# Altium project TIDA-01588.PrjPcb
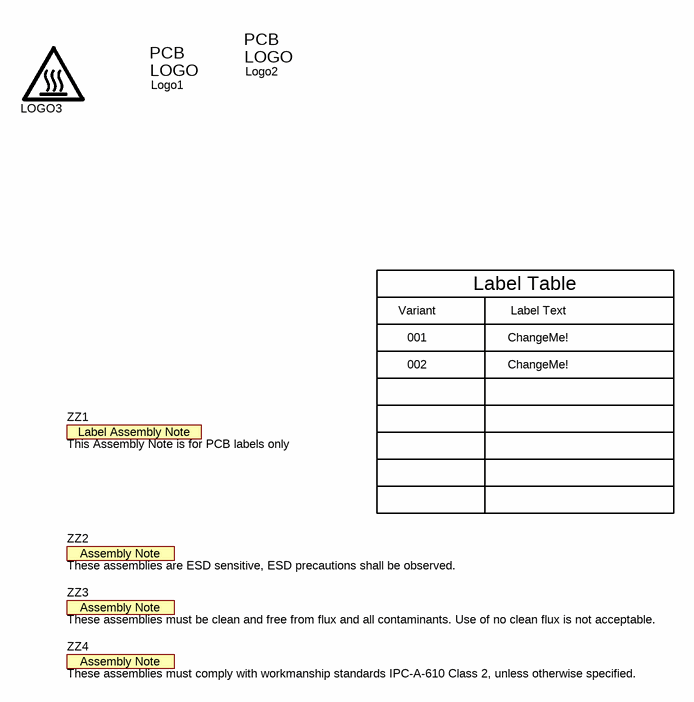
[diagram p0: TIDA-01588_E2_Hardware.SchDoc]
CopyrightYear: 2017; EVM_orderable: N/A; PCB_Layout: Manu; PCB_Rev: E2; PRJ_Customer: Public Release; PRJ_Engineer: Manu Balakrishnan; PRJ_Number: TIDA-01588; PRJ_Title: 10.8-V/15-W, Power Stage for Brushed DC Servo; SCH_Rev: E2; TechSupport: http://www.ti.com/support; TID: TIDA-01588
3 sheets, 50 parts. Net scope: global (net labels, ports and power ports of the same name join across sheets).
Board file: TIDA-01588_PCB.PcbDoc
Sheets:
  TIDA-01588_E2_CoverSheet.SchDoc
  TIDA-01588_E2_Hardware.SchDoc
  TIDA-01588_E2_Sheet1.SchDoc

## Sheet TIDA-01588_E2_CoverSheet.SchDoc
size 431 x 279 mm; Date: Not shown in title block; ApprovedBy: Not shown in title block; CheckedBy: Not shown in title block; Author: Not shown in title block; CompanyName: Not shown in title block; DrawnBy: Manu; Engineer: Not shown in title block; Organization: Not shown in title block; Address1: Not shown in title block; Address2: Not shown in title block; Address3: Not shown in title block; Address4: Not shown in title block; DocumentNumber: 1; Revision: Use project parameter SCH_Rev; SheetNumber: 1; SheetTotal: 3; PageSetup: Record=PageOptions¦CenterHorizontal=True¦CenterVertical=True¦PrintScale=1.00¦XCorrection=1.00¦YCorrection=1.00¦PrintKind=0¦BorderSize=5000000¦LeftOffset=0¦BottomOffset=0¦Orientation=2¦PaperLength=1000¦PaperWidth=1000¦Scale=100¦PaperSource=15¦PrintQuality=600¦MediaType=1¦DitherType=10¦PaperKind=Letter¦PrintScaleMode=1

## Sheet TIDA-01588_E2_Hardware.SchDoc
size 431 x 279 mm; Date: Not shown in title block; ApprovedBy: Not shown in title block; CheckedBy: Not shown in title block; Author: Not shown in title block; CompanyName: Not shown in title block; DrawnBy: Manu; Engineer: Not shown in title block; Organization: Not shown in title block; Address1: Not shown in title block; Address2: Not shown in title block; Address3: Not shown in title block; Address4: Not shown in title block; DocumentNumber: 1; Revision: Use project parameter SCH_Rev; SheetNumber: 3; SheetTotal: 3; PageSetup: Record=PageOptions¦CenterHorizontal=True¦CenterVertical=True¦PrintScale=1.00¦XCorrection=1.00¦YCorrection=1.00¦PrintKind=0¦BorderSize=5000000¦LeftOffset=0¦BottomOffset=0¦Orientation=2¦PaperLength=1000¦PaperWidth=1000¦Scale=100¦PaperSource=15¦PrintQuality=600¦MediaType=1¦DitherType=10¦PaperKind=Letter¦PrintScaleMode=1

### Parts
Logo1  ESD Susceptible  [ESD_Overlay_small]  (value not drawn)  (no BOM)
Logo2  Pb-Free Symbol  [Pb-Free_Overlay_small]  (value not drawn)  (no BOM)
LOGO3  CAUTION HOT SURFACE  [IEC_HotSurface_small]  (value not drawn)  (no BOM)
ZZ1  This Assembly Note is for PCB labels only  [AssemblyNoteLabel]  (no BOM)
ZZ2  These assemblies are ESD sensitive, ESD precautions shall be observed.  [AssemblyNote]  (no BOM)
ZZ3  These assemblies must be clean and free from flux and all contaminants. Use of no clean flux is not acceptable.  [AssemblyNote]  (no BOM)
ZZ4  These assemblies must comply with workmanship standards IPC-A-610 Class 2, unless otherwise specified.  [AssemblyNote]  (no BOM)

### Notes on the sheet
- Variant
- 001
- Label Table
- Label Text
- ChangeMe!
- 002

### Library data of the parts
Logo1 = ESD_Susceptible: ESD Susceptible Symbol; SymbolCreator: a0412235
Logo2 = Pb-Free: SymbolCreator: a0412235
LOGO3 = IEC_HotSurface: IEC 61010-1 Hot Surface Warning; SymbolCreator: a0412235
ZZ1 = AssemblyNoteLabel: SymbolCreator: a0412235
ZZ2-ZZ4 = AssemblyNote: SymbolCreator: codlsc

## Sheet TIDA-01588_E2_Sheet1.SchDoc: Sheet1
size 431 x 279 mm; Date: Not shown in title block; ApprovedBy: Not shown in title block; CheckedBy: Not shown in title block; Author: Not shown in title block; CompanyName: Not shown in title block; DrawnBy: Manu; Engineer: Manu; Organization: Not shown in title block; Address1: Not shown in title block; Address2: Not shown in title block; Address3: Not shown in title block; Address4: Not shown in title block; DocumentNumber: 1; Revision: Use project parameter SCH_Rev; SheetNumber: 2; SheetTotal: 3; PageSetup: Record=PageOptions¦CenterHorizontal=True¦CenterVertical=True¦PrintScale=1.00¦XCorrection=1.00¦YCorrection=1.00¦PrintKind=0¦BorderSize=5000000¦LeftOffset=0¦BottomOffset=0¦Orientation=2¦PaperLength=1000¦PaperWidth=1000¦Scale=100¦PaperSource=15¦PrintQuality=600¦MediaType=1¦DitherType=10¦PaperKind=Letter¦PrintScaleMode=1
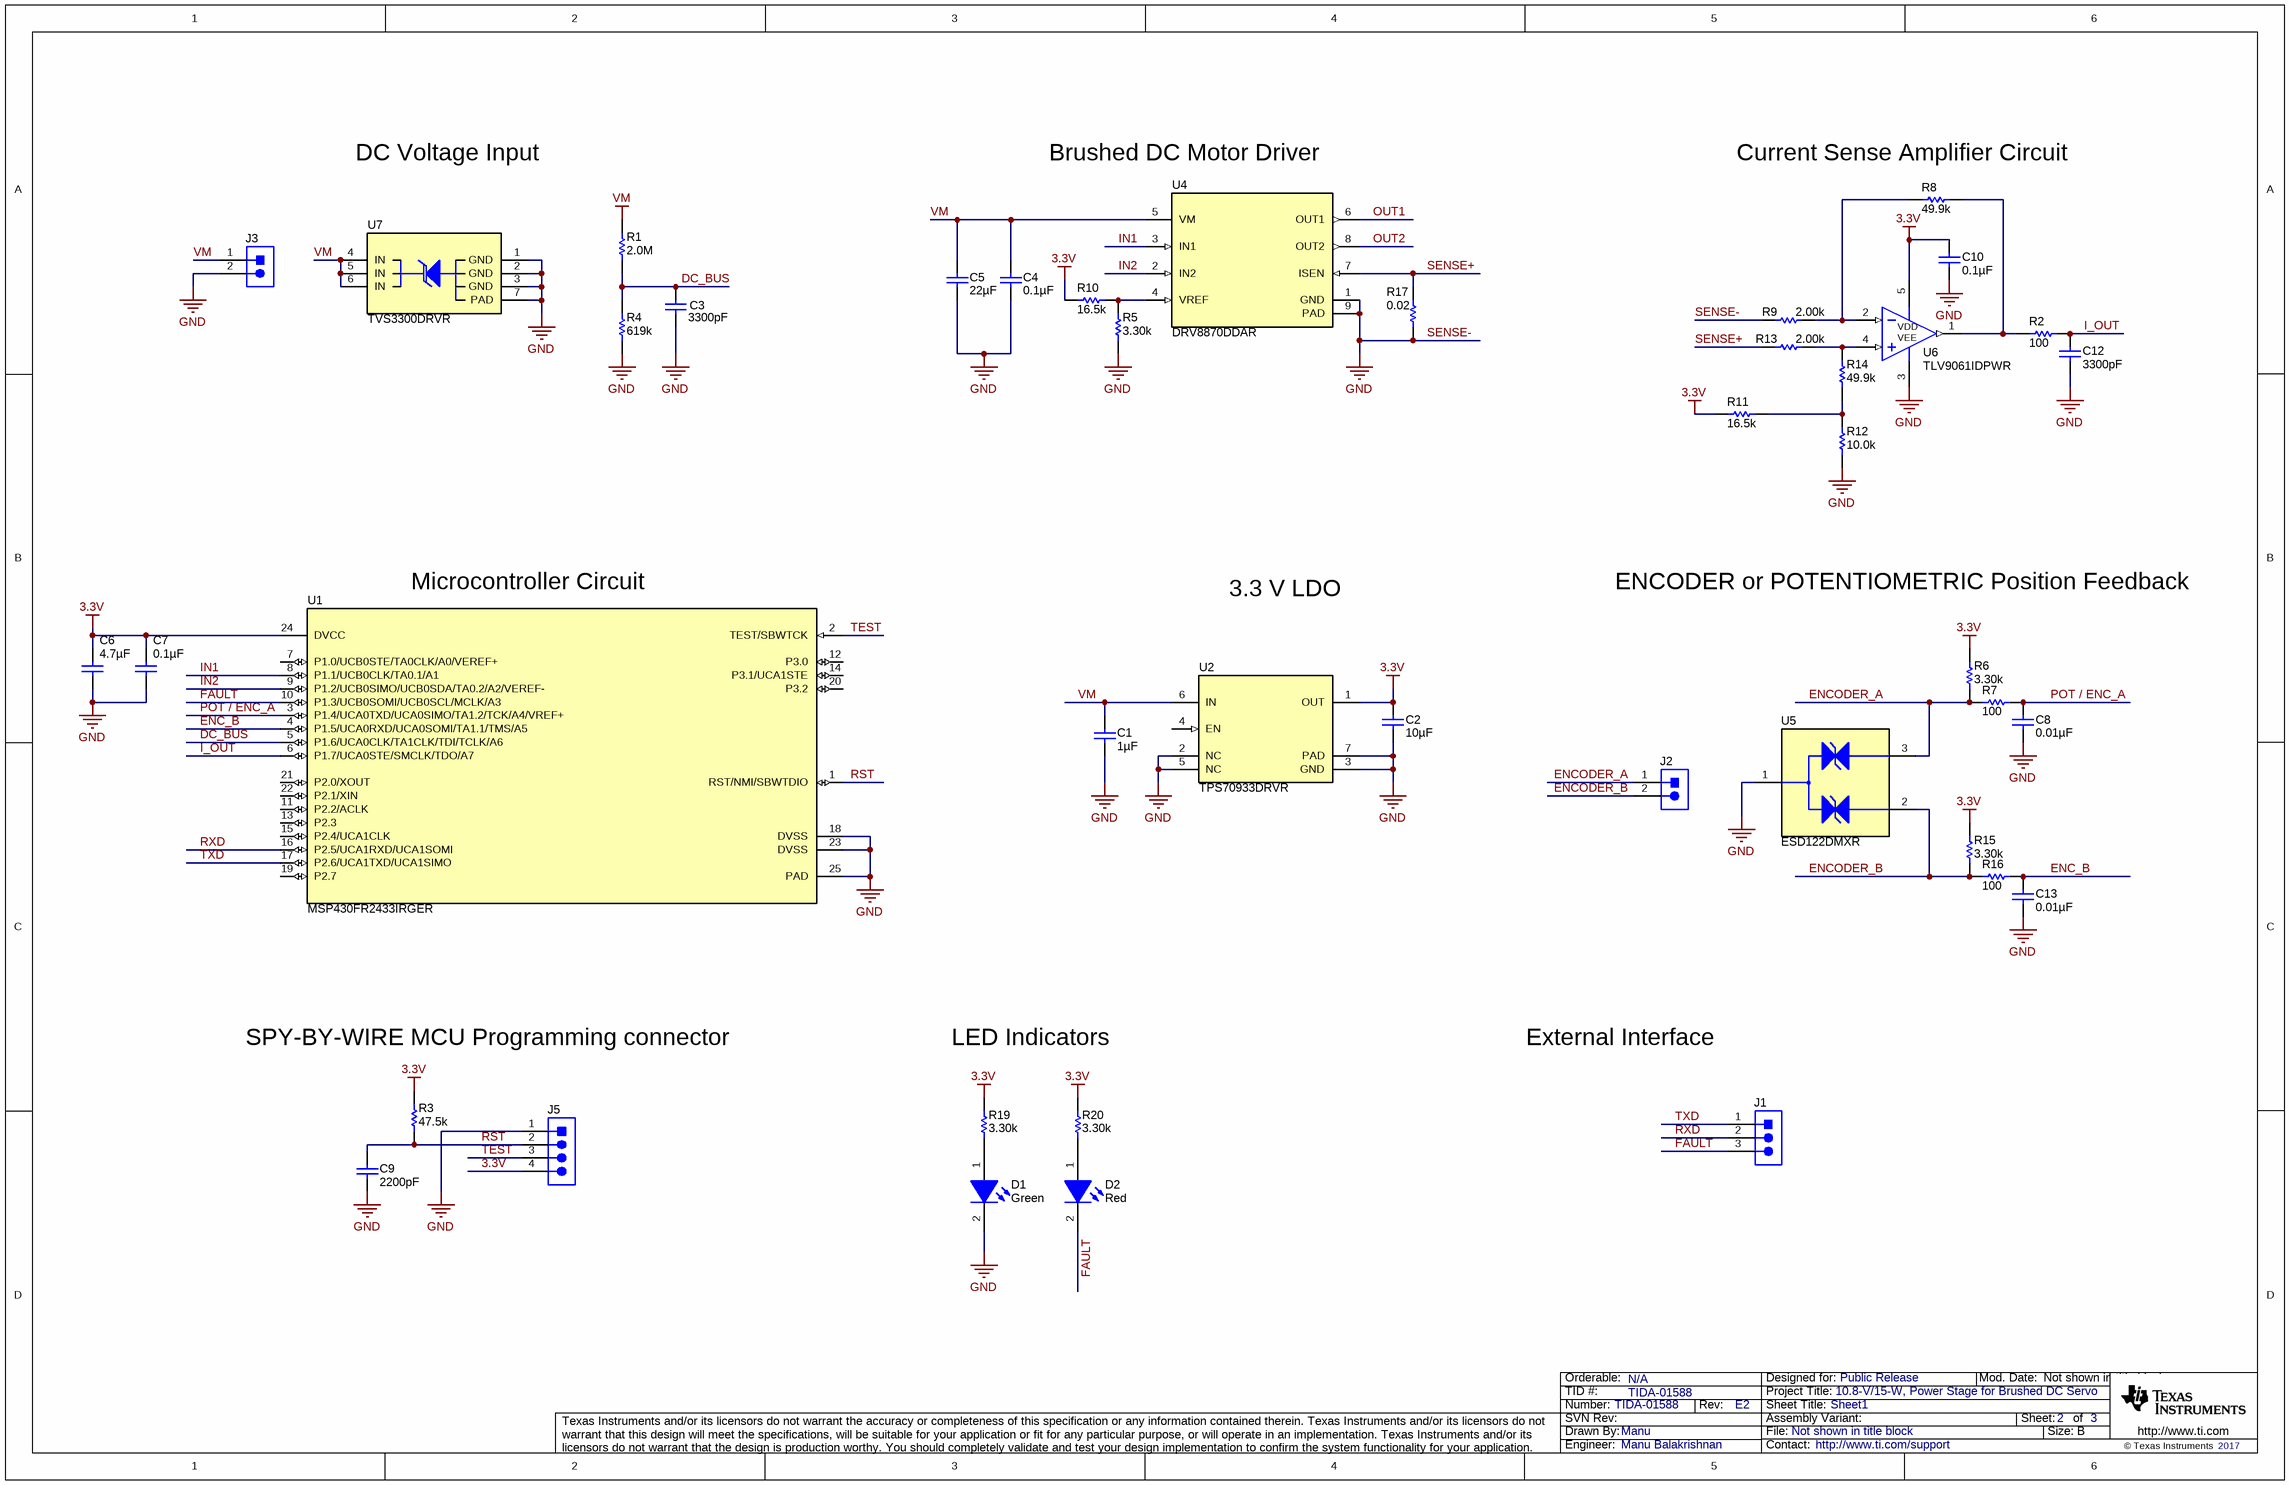
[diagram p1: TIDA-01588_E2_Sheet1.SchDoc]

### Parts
C1  ValueDisplayed: 1µF  [0402]  (hidden comment: GRM155R6YA105ME11D)
C2  ValueDisplayed: 10µF  [0603]  (hidden comment: C1608JB0J106K080AB)
C3  ValueDisplayed: 3300pF  [0201]  (hidden comment: GRM033R70J332KA01D)
C4  ValueDisplayed: 0.1µF  [0402]  (hidden comment: C1005X7R1H104K050BE)
C5  ValueDisplayed: 22µF  [1206_180]  (hidden comment: C3216X5R1V226M160AC)
C6  ValueDisplayed: 4.7µF  [0603]  (hidden comment: GRM188R60J475KE19D)
C7  ValueDisplayed: 0.1µF  [0402]  (hidden comment: GRM155R70J104KA01D)
C8  ValueDisplayed: 0.01µF  [0201]  (hidden comment: GRM033R71A103KA01D)
C9  ValueDisplayed: 2200pF  [0201]  (hidden comment: GRM033R71A222KA01D)
C10  ValueDisplayed: 0.1µF  [0402]  (hidden comment: GRM155R70J104KA01D)
C12  ValueDisplayed: 3300pF  [0201]  (hidden comment: GRM033R70J332KA01D)
C13  ValueDisplayed: 0.01µF  [0201]  (hidden comment: GRM033R71A103KA01D)
D1  value Green  [APHHS1005_Green]  (hidden comment: APHHS1005CGCK)
D2  value Red  [APHHS1005_Red]  (hidden comment: APHHS1005SURCK)
J1  GRPB031VWVN-RC  [Sullins_GRPB031VWVN-RC]  (value not drawn)
J2  GRPB021VWVN-RC  [Sullins_GRPB021VWVN-RC]  (value not drawn)
J3  GRPB021VWVN-RC  [Sullins_GRPB021VWVN-RC]  (value not drawn)
J5  GRPB041VWVN-RC  [Sullins_GRPB041VWVN-RC]  (value not drawn)
R1  ValueDisplayed: 2.0M  [0402]  (hidden comment: RC0402JR-072ML)
R2  ValueDisplayed: 100  [0201]  (hidden comment: RC0201JR-07100RL)
R3  ValueDisplayed: 47.5k  [0201]  (hidden comment: RC0201FR-0747K5L)
R4  ValueDisplayed: 619k  [0201]  (hidden comment: RC0201FR-07619KL)
R5  ValueDisplayed: 3.30k  [0201]  (hidden comment: RC0201FR-073K3L)
R6  ValueDisplayed: 3.30k  [0201]  (hidden comment: RC0201FR-073K3L)
R7  ValueDisplayed: 100  [0201]  (hidden comment: RC0201JR-07100RL)
R8  ValueDisplayed: 49.9k  [0201]  (hidden comment: RC0201FR-0749K9L)
R9  ValueDisplayed: 2.00k  [0201]  (hidden comment: RC0201FR-072KL)
R10  ValueDisplayed: 16.5k  [0201]  (hidden comment: RC0201FR-0716K5L)
R11  ValueDisplayed: 16.5k  [0201]  (hidden comment: RC0201FR-0716K5L)
R12  ValueDisplayed: 10.0k  [0201]  (hidden comment: RC0201FR-0710KL)
R13  ValueDisplayed: 2.00k  [0201]  (hidden comment: RC0201FR-072KL)
R14  ValueDisplayed: 49.9k  [0201]  (hidden comment: RC0201FR-0749K9L)
R15  ValueDisplayed: 3.30k  [0201]  (hidden comment: RC0201FR-073K3L)
R16  ValueDisplayed: 100  [0201]  (hidden comment: RC0201JR-07100RL)
R17  ValueDisplayed: 0.02  [1206]  (hidden comment: CSR1206FK20L0)
R19  ValueDisplayed: 3.30k  [0201]  (hidden comment: RC0201FR-073K3L)
R20  ValueDisplayed: 3.30k  [0201]  (hidden comment: RC0201FR-073K3L)
U1  MSP430FR2433IRGER  [RGE0024H]
U2  TPS70933DRVR  [DRV0006A]
U4  DRV8870DDAR  [DDA0008E_N]
U5  ESD122DMXR  [DMX0003A]
U6  TLV9061IDPWR  [DPW0005A]
U7  TVS3300DRVR  [DRV0006A]

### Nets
3.3V: C2.2 C6.1 C7.1 C10.1 J5.4 R3.2 R6.2 R10.2 R11.1 R15.2 R19.2 R20.2 U1.24(DVCC) U2.1(OUT) U6.5(VCC)
SENSE-: C1.2 C2.1 C3.2 C4.1 C5.2 C6.2 C7.2 C8.2 C9.2 C10.2 C12.2 C13.2 D1.2(K) J3.2 J5.1 R4.1 R5.1 R9.1 R12.1 R17.1 U1.18(DVSS) U1.23(DVSS) U1.25(PAD) U2.2(NC) U2.3(GND) U2.5(NC) U2.7(PAD) U4.1(GND) U4.9(PAD) U5.1(GND) U6.3(VEE) U7.1(GND) U7.2(GND) U7.3(GND) U7.7(PAD)  [also labelled GND]
VM: C1.1 C4.2 C5.1 J3.1 R1.2 U2.6(IN) U4.5(VM) U7.4(IN) U7.5(IN) U7.6(IN)
DC_BUS: C3.1 R1.1 R4.2 U1.5(P1.6/UCA0CLK/TA1CLK/TDI/TCLK/A6)
ENC_B: C13.1 R16.2 U1.4(P1.5/UCA0RXD/UCA0SOMI/TA1.1/TMS/A5)
ENCODER_A: J2.1 R6.1 R7.1 U5.3(IO1)
ENCODER_B: J2.2 R15.1 R16.1 U5.2(IO2)
FAULT: D2.2(K) J1.3 U1.10(P1.3/UCB0SOMI/UCB0SCL/MCLK/A3)
I_OUT: C12.1 R2.2 U1.6(P1.7/UCA0STE/SMCLK/TDO/A7)
IN1: U1.8(P1.1/UCB0CLK/TA0.1/A1) U4.3(IN1)
IN2: U1.9(P1.2/UCB0SIMO/UCB0SDA/TA0.2/A2/VEREF-) U4.2(IN2)
OUT1: U4.6(OUT1)
OUT2: U4.8(OUT2)
POT / ENC_A: C8.1 R7.2 U1.3(P1.4/UCA0TXD/UCA0SIMO/TA1.2/TCK/A4/VREF+)
RST: C9.1 J5.2 R3.1 U1.1(RST/NMI/SBWTDIO)
RXD: J1.2 U1.16(P2.5/UCA1RXD/UCA1SOMI)
SENSE+: R13.1 R17.2 U4.7(ISEN)
TEST: J5.3 U1.2(TEST/SBWTCK)
TXD: J1.1 U1.17(P2.6/UCA1TXD/UCA1SIMO)
NetD1_1: D1.1(A) R19.1
NetD2_1: D2.1(A) R20.1
NetR2_1: R2.1 R8.2 U6.1(OUT)
NetR5_2: R5.2 R10.1 U4.4(VREF)
NetR8_1: R8.1 R9.2 U6.2(IN-)
NetR11_2: R11.2 R12.2 R14.1
NetR13_2: R13.2 R14.2 U6.4(IN+)

Not connected (* = marked no-connect by the designer): U1 7(P1.0/UCB0STE/TA0CLK/A0/VEREF+) 11(P2.2/ACLK) 12(P3.0) 13(P2.3) 14(P3.1/UCA1STE) 15(P2.4/UCA1CLK) 19(P2.7) 20(P3.2) 21(P2.0/XOUT) 22(P2.1/XIN); U2 4(EN)

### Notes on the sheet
- DC Voltage Input
- Brushed DC Motor Driver
- (near R8) Current Sense Amplifier Circuit
- (near U1) Microcontroller Circuit
- 3.3 V LDO
- ENCODER or POTENTIOMETRIC Position Feedback
- SPY-BY-WIRE MCU Programming connector
- LED Indicators
- External Interface

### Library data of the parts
C1 = GRM155R6YA105ME11D: CAP, CERM, 1 µF, 35 V,+/- 20%, X5R, 0402; Manufacturer: MuRata; Polarized: N; CompType: Capacitor; Value: 1uF; U/M: EA; Cap_F: 0.000001; Tolerance_%: 20; VDC_V: 35; Value2: 35V; TaMin_C: -55; TaMax_C: 85; SizeArea_mm2: 0.5; SizeAreaWB_mm2: 3; SizeX_mm: 1; SizeZ_mm: 0.6; AEC Category: Q200
C2 = C1608JB0J106K080AB: CAP, CERM, 10 µF, 6.3 V,+/- 10%, JB, 0603; Manufacturer: TDK; Polarized: N; CompType: Capacitor; Value: 10uF; U/M: EA; Cap_F: 0.00001; Tolerance_%: 10; VDC_V: 6.3; Value2: 6.3V; TaMin_C: -25; TaMax_C: 85; SizeArea_mm2: 1.28; SizeAreaWB_mm2: 4.68; SizeX_mm: 1.6; SizeY_mm: 0.8; SizeZ_mm: 1; AEC Category: Q200
C3 C12 = GRM033R70J332KA01D: CAP, CERM, 3300 pF, 6.3 V,+/- 10%, X7R, 0201; Manufacturer: MuRata; Polarized: N; CompType: Capacitor; Value: 3300pF; U/M: EA; Cap_F: 0.0000000033; Tolerance_%: 10; VDC_V: 6.3; Value2: 6.3V; TaMin_C: -55; TaMax_C: 125; SizeArea_mm2: 0.18; SizeAreaWB_mm2: 2.08; SizeX_mm: 0.6; SizeY_mm: 0.3; SizeZ_mm: 0.26; AEC Category: Q200
C4 = C1005X7R1H104K050BE: CAP, CERM, 0.1 µF, 50 V,+/- 10%, X7R, 0402; Manufacturer: TDK; Polarized: N; CompType: Capacitor; Value: 0.1uF; U/M: EA; Cap_F: 0.0000001; Tolerance_%: 10; VDC_V: 50; Value2: 50V; TaMin_C: -55; TaMax_C: 125; SizeArea_mm2: 0.5; SizeAreaWB_mm2: 3; SizeX_mm: 1; SizeZ_mm: 0.6; AEC Category: Q200; Green_Lifecycle: Active; Green_REACh: Passed
C5 = C3216X5R1V226M160AC: CAP, CERM, 22 µF, 35 V,+/- 20%, X5R, 1206; Manufacturer: TDK; Polarized: N; CompType: Capacitor; Value: 22uF; U/M: EA; Cap_F: 0.000022; Tolerance_%: 20; ESR_ohm: 0.002398; Value1: 0.002398 ohm; VDC_V: 35; Value2: 35V; IRMS_A: 4.68507; TaMin_C: -55; TaMax_C: 85; Cap_Case: 1206; SizeArea_mm2: 5.12; SizeAreaWB_mm2: 10.92; SizeX_mm: 3.2; SizeY_mm: 1.6; SizeZ_mm: 1.8; AEC Category: Q200; Green_Lifecycle: Active; Green_REACh: Passed
C6 = GRM188R60J475KE19D: CAP, CERM, 4.7 µF, 6.3 V,+/- 10%, X5R, 0603; Manufacturer: MuRata; Polarized: N; CompType: Capacitor; Value: 4.7uF; U/M: EA; Cap_F: 0.0000047; Tolerance_%: 10; ESR_ohm: 0.005; Value1: 0.005 ohm; VDC_V: 6.3; Value2: 6.3V; IRMS_A: 2; TaMin_C: -55; TaMax_C: 85; SizeArea_mm2: 1.28; SizeAreaWB_mm2: 4.68; SizeX_mm: 1.6; SizeY_mm: 0.8; SizeZ_mm: 1; AEC Category: Q200; Green_Lifecycle: Active; Green_REACh: Passed
C7 C10 = GRM155R70J104KA01D: CAP, CERM, 0.1 µF, 6.3 V,+/- 10%, X7R, 0402; Manufacturer: MuRata; Polarized: N; CompType: Capacitor; Value: 0.1uF; U/M: EA; Cap_F: 0.0000001; Tolerance_%: 10; VDC_V: 6.3; Value2: 6.3V; TaMin_C: -55; TaMax_C: 125; SizeArea_mm2: 0.5; SizeAreaWB_mm2: 3; SizeX_mm: 1; SizeZ_mm: 0.6; AEC Category: Q200; Green_Lifecycle: Active; Green_REACh: Passed
C8 C13 = GRM033R71A103KA01D: CAP, CERM, 0.01 µF, 10 V,+/- 10%, X7R, 0201; Manufacturer: MuRata; Polarized: N; CompType: Capacitor; Value: 0.01uF; U/M: EA; Cap_F: 0.00000001; Tolerance_%: 10; Value2: 10V; TaMin_C: -55; TaMax_C: 125; SizeArea_mm2: 0.18; SizeAreaWB_mm2: 2.08; SizeX_mm: 0.6; SizeY_mm: 0.3; SizeZ_mm: 0.26; AEC Category: Q200; Green_Lifecycle: Active; Green_REACh: Passed
C9 = GRM033R71A222KA01D: CAP, CERM, 2200 pF, 10 V,+/- 10%, X7R, 0201; Manufacturer: MuRata; Polarized: N; CompType: Capacitor; Value: 2200pF; U/M: EA; Cap_F: 0.0000000022; Tolerance_%: 10; Value2: 10V; TaMin_C: -55; TaMax_C: 125; SizeArea_mm2: 0.18; SizeAreaWB_mm2: 2.08; SizeX_mm: 0.6; SizeY_mm: 0.3; SizeZ_mm: 0.26; AEC Category: Q200
D1 = APHHS1005CGCK: LED, Green, SMD; Manufacturer: Kingbright; Vf_V: 2.1; Value2: 2.1V; Io_A: 0.02; Vr_V: 5; Ir_A: 1e-005; Tjmax_C: 85; Power_TotalModule: 0.075; Value1: 0.075W; Angle: 120; SizeAreaWB_mm2: 3; SizeArea_mm2: 0.5; SizeX_mm: 1; SizeZ_mm: 0.6; U/M: EA
D2 = APHHS1005SURCK: LED, Red, SMD; Manufacturer: Kingbright; Vf_V: 1.95; Value2: 1.95V; Io_A: 0.02; Vr_V: 5; Ir_A: 1e-005; Tjmax_C: 85; Power_TotalModule: 0.075; Value1: 0.075W; Angle: 120; SizeAreaWB_mm2: 3; SizeArea_mm2: 0.5; SizeX_mm: 1; SizeZ_mm: 0.6; U/M: EA
J1 = GRPB031VWVN-RC: Header, 50mil, 3x1, Gold, TH; Manufacturer: Sullins Connector Solutions; SymbolCreator: a0799628; Gender: Male; Shrouded: N; Row_Count: 1; Green_Lifecycle: Not Set; Green_REACh: Incomplete
J2 J3 = GRPB021VWVN-RC: Header, 50mil, 2x1, Gold, TH; Manufacturer: Sullins Connector Solutions; SymbolCreator: a0412235; Green_Lifecycle: Not Set; Green_REACh: Incomplete
J5 = GRPB041VWVN-RC: Header, 50mil, 4x1, Gold, TH; Manufacturer: Sullins Connector Solutions; SymbolCreator: a0412235; Green_Lifecycle: Not Set; Green_REACh: Incomplete
R1 = CRCW04022M00JNED: RES SMD 2M OHM 5% 1/16W 0402; Manufacturer: Yageo; CompType: Resistor; Value: 2.0Meg; Res_ohm: 2000000; Value_Code: 2M00; Tolerance_%: 5; Power_W: 0.063; Value2: 0.063W; VDC_V: 50; TempCo: 200 ppm/C; SizeArea_mm2: 0.5; SizeX_mm: 1; SizeZ_mm: 0.6; EIA_Code: E24; U/M: EA; AEC Category: Q200
R2 R7 R16 = RC0201JR-07100RL: RES, 100, 5%, 0.05 W, 0201; Manufacturer: Yageo America; CompType: Resistor; Value: 100; Value_Code: 100R; Tolerance_%: 5; Power_W: 0.05; Value2: 0.05W; VDC_V: 25; TempCo: 200 ppm/C; SizeArea_mm2: 0.18; SizeX_mm: 0.6; SizeY_mm: 0.3; SizeZ_mm: 0.26; EIA_Code: E24; U/M: EA; AEC Category: Q200; AEC Qualified: N
R3 = RC0201FR-0747K5L: RES, 47.5 k, 1%, 0.05 W, 0201; Manufacturer: Yageo America; CompType: Resistor; Value: 47.5k; Res_ohm: 47500; Value_Code: 47k5; Tolerance_%: 1; Power_W: 0.05; Value2: 0.05W; VDC_V: 25; TempCo: 200 ppm/C; SizeArea_mm2: 0.18; SizeX_mm: 0.6; SizeY_mm: 0.3; SizeZ_mm: 0.26; EIA_Code: E96; U/M: EA; AEC Category: Q200; AEC Qualified: N
R4 = RC0201FR-07619KL: RES, 619 k, 1%, 0.05 W, 0201; Manufacturer: Yageo America; CompType: Resistor; Value: 619k; Res_ohm: 619000; Tolerance_%: 1; Power_W: 0.05; Value2: 0.05W; VDC_V: 25; TempCo: 200 ppm/C; SizeArea_mm2: 0.18; SizeX_mm: 0.6; SizeY_mm: 0.3; SizeZ_mm: 0.26; EIA_Code: E96; U/M: EA; AEC Category: Q200; AEC Qualified: N
R5 R6 R15 R19 R20 = RC0201FR-073K3L: RES, 3.30 k, 1%, 0.05 W, 0201; Manufacturer: Yageo America; CompType: Resistor; Value: 3.30k; Res_ohm: 3300; Value_Code: 3k30; Tolerance_%: 1; Power_W: 0.05; Value2: 0.05W; VDC_V: 25; TempCo: 200 ppm/C; SizeArea_mm2: 0.18; SizeX_mm: 0.6; SizeY_mm: 0.3; SizeZ_mm: 0.26; U/M: EA; AEC Category: Q200; AEC Qualified: N
R8 R14 = RC0201FR-0749K9L: RES, 49.9 k, 1%, 0.05 W, 0201; Manufacturer: Yageo America; CompType: Resistor; Value: 49.9k; Res_ohm: 49900; Value_Code: 49k9; Tolerance_%: 1; Power_W: 0.05; Value2: 0.05W; VDC_V: 25; TempCo: 200 ppm/C; SizeArea_mm2: 0.18; SizeX_mm: 0.6; SizeY_mm: 0.3; SizeZ_mm: 0.26; EIA_Code: E96; U/M: EA; AEC Category: Q200; AEC Qualified: N
R9 R13 = RC0201FR-072KL: RES, 2.00 k, 1%, 0.05 W, 0201; Manufacturer: Yageo America; CompType: Resistor; Value: 2.00k; Res_ohm: 2000; Value_Code: 2k00; Tolerance_%: 1; Power_W: 0.05; Value2: 0.05W; VDC_V: 25; TempCo: 200 ppm/C; SizeArea_mm2: 0.18; SizeX_mm: 0.6; SizeY_mm: 0.3; SizeZ_mm: 0.26; EIA_Code: E96; U/M: EA; AEC Category: Q200; AEC Qualified: N
R10 R11 = RC0201FR-0716K5L: RES, 16.5 k, 1%, 0.05 W, 0201; Manufacturer: Yageo America; CompType: Resistor; Value: 16.5k; Res_ohm: 16500; Value_Code: 16k5; Tolerance_%: 1; Power_W: 0.05; Value2: 0.05W; VDC_V: 25; TempCo: 200 ppm/C; SizeArea_mm2: 0.18; SizeX_mm: 0.6; SizeY_mm: 0.3; SizeZ_mm: 0.26; EIA_Code: E96; U/M: EA; AEC Category: Q200; AEC Qualified: N
R12 = RC0201FR-0710KL: RES, 10.0 k, 1%, 0.05 W, 0201; Manufacturer: Yageo America; CompType: Resistor; Value: 10.0k; Res_ohm: 10000; Value_Code: 10k0; Tolerance_%: 1; Power_W: 0.05; Value2: 0.05W; VDC_V: 25; TempCo: 200 ppm/C; SizeArea_mm2: 0.18; SizeX_mm: 0.6; SizeY_mm: 0.3; SizeZ_mm: 0.26; EIA_Code: E96; U/M: EA; AEC Category: Q200; AEC Qualified: N
R17 = CSR1206FK20L0: RES, 0.02, 1%, 0.5 W, 1206; Manufacturer: Stackpole Electronics Inc; CompType: Resistor; Value: 0.02; Value_Code: R020; Tolerance_%: 1; Power_W: 0.5; Value2: 0.5W; TempCo: 100 ppm/C; SizeArea_mm2: 5.12; SizeX_mm: 3.2; SizeY_mm: 1.6; SizeZ_mm: 1.35; EIA_Code: E96; U/M: EA; AEC Category: Q200
U1 = MSP430FR2433IRGER: MSP430FR2433 16 MHz Ultra-Low-Power Microcontroller with 16 KB FRAM, 4 KB RAM, 19 IO, 4 Timers, RGE0024H (VQFN-24); Alternate PartNumber: MSP430FR2433IRGET; Manufacturer: Texas Instruments; SymbolCreator: Altium; SizeArea_mm2: 16; SizeAreaWB_mm2: 25; SizeX_mm: 4; SizeZ_mm: 1; CompType: IC; U/M: EA
U2 = TPS70933DRVR: 150-mA, 30-V, Ultra-Low IQ, Wide Input Low-Dropout Regulator with Reverse Current Protection, DRV0006A (WSON-6); Alternate PartNumber: TPS70933DRVT; Manufacturer: Texas Instruments; SymbolCreator: a0411947; SizeArea_mm2: 4; SizeAreaWB_mm2: 9; SizeX_mm: 2; SizeZ_mm: 0.8; CompType: IC; U/M: EA; Green_Lifecycle: Active; Green_REACh: Passed
U4 = DRV8870DDAR: 3.6A Brushed DC Motor Driver (PWM Ctrl), DDA0008E (SOIC-8); Manufacturer: Texas Instruments; SymbolCreator: Altium; SizeArea_mm2: 31; SizeAreaWB_mm2: 57.4; SizeX_mm: 5; SizeY_mm: 6.2; SizeZ_mm: 1.7; CompType: IC; U/M: EA
U5 = ESD122DMXR: 2-Channel ESD Protection Diode for USB Type-C and HDMI 2.0, DMX0003A (X2SON-3); Manufacturer: Texas Instruments; SymbolCreator: Altium; SizeArea_mm2: 0.6; SizeAreaWB_mm2: 3.2; SizeY_mm: 1; SizeZ_mm: 0.4; CompType: IC; U/M: EA
U6 = TLV9061DPW: TLV9061DPW, DPW0005A (X2SON-5); Manufacturer: Texas Instruments; SymbolCreator: a0412235; SizeArea_mm2: 0.64; SizeAreaWB_mm2: 3.24; SizeX_mm: 0.8; SizeZ_mm: 0.4; CompType: IC; U/M: EA
U7 = TVS3300DRVR: 33V Precision Surge Protection Clamp, DRV0006A (WSON-6); Alternate PartNumber: TVS3300DRVT; Manufacturer: Texas Instruments; SymbolCreator: Altium; SizeArea_mm2: 4; SizeAreaWB_mm2: 9; SizeX_mm: 2; SizeZ_mm: 0.8; CompType: IC; U/M: EA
